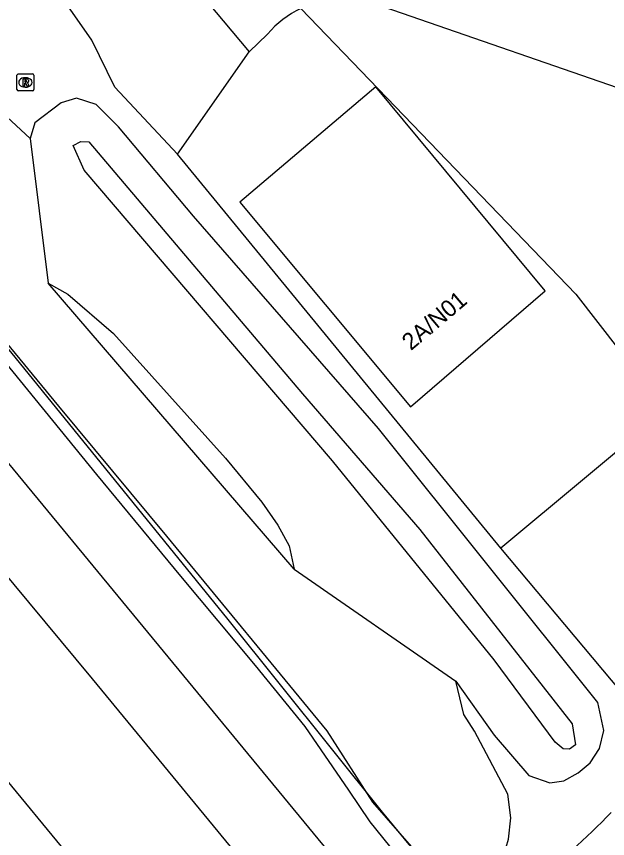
# Model space of a CAD drawing. Extents: x 158132 to 159658, y 385257 to 387209.
# Drawn here: x 159265.1 to 159300.11, y 385281.7 to 385330.4 of the extents above; entities that cross this region are included whole.
import ezdxf

# ---------------------------------------------------------------- set-up
doc = ezdxf.new("R2010")
doc.units = 0
for name, color, linetype in [('IMGEO_Geluidsscherm', 7, 'Continuous'), ('IMGEO_Grasland_overig', 7, 'Continuous'), ('IMGEO_Groenvoorziening', 7, 'Continuous'), ('IMGEO_Pand', 7, 'Continuous'), ('IMGEO_Pand_nummerreeks', 7, 'Continuous'), ('IMGEO_Rijbaan_lokaal_gesloten', 7, 'Continuous'), ('IMGEO_Rijbaan_lokaal_open', 7, 'Continuous'), ('IMGEO_Rioolput', 7, 'Continuous'), ('IMGEO_Spoor', 7, 'Continuous'), ('IMGEO_Spoorbaan_halfverhard', 7, 'Continuous'), ('IMGEO_Struiken', 7, 'Continuous'), ('IMGEO_Voetpad_open', 7, 'Continuous'), ('IMGEO_Waterloop', 7, 'Continuous')]:
    doc.layers.add(name, color=color, linetype=linetype)

msp = doc.modelspace()

# ---------------------------------------------------------------- linework, layer by layer
at = {"layer": 'IMGEO_Geluidsscherm'}
for points in [[(159286.211, 385283.865), (159283.499, 385288.078), (159274.005, 385299.62), (159267.615, 385307.323), (159258.062, 385318.911), (159242.144, 385338.211), (159232.644, 385349.825), (159223.238, 385361.455), (159210.649, 385376.979), (159201.186, 385388.692), (159191.801, 385400.335), (159182.407, 385412.048), (159166.93, 385431.293), (159161.29, 385438.364)], [(159296.997, 385270.945), (159292.991, 385275.788), (159288.498, 385281.229), (159286.211, 385283.865)]]:
    msp.add_lwpolyline(points, dxfattribs=at)
at = {"layer": 'IMGEO_Grasland_overig'}
for points in [[(159291.119, 385291.018), (159293.396, 385287.829), (159295.457, 385285.447), (159296.697, 385285.002), (159297.523, 385285.119), (159298.364, 385285.595), (159299.082, 385286.185), (159299.634, 385287.039), (159299.891, 385288.107), (159299.54, 385289.761), (159286.549, 385305.997), (159275.58, 385318.577), (159271.141, 385323.855), (159269.821, 385325.184), (159268.653, 385325.56), (159267.742, 385325.27), (159266.182, 385324.102), (159265.905, 385323.162)], [(159293.797, 385298.904), (159274.632, 385322.244)], [(159266.982, 385314.602), (159268.141, 385313.945), (159270.859, 385311.624), (159277.476, 385304.236), (159279.635, 385301.634), (159280.576, 385300.258), (159281.255, 385299.039), (159281.559, 385297.663)], [(159303.628, 385287.17), (159293.797, 385298.904)]]:
    msp.add_lwpolyline(points, dxfattribs=at)
at = {"layer": 'IMGEO_Groenvoorziening'}
msp.add_lwpolyline([(159281.95, 385330.865), (159298.235, 385313.951), (159303.578, 385307.059), (159293.797, 385298.904)], dxfattribs=at)
at = {"layer": 'IMGEO_Pand'}
msp.add_lwpolyline([(159286.379, 385326.224), (159278.322, 385319.396), (159288.437, 385307.269), (159296.42, 385314.151), (159286.379, 385326.224)], dxfattribs=at)
at = {"layer": 'IMGEO_Rijbaan_lokaal_gesloten'}
for points in [[(159271.887, 385336.661), (159278.893, 385328.292)], [(159274.632, 385322.244), (159270.926, 385326.201), (159269.57, 385328.991), (159267.594, 385331.826), (159265.132, 385334.674)], [(159274.632, 385322.244), (159278.893, 385328.292)]]:
    msp.add_lwpolyline(points, dxfattribs=at)
at = {"layer": 'IMGEO_Rijbaan_lokaal_open'}
for points in [[(159312.983, 385321.919), (159302.29, 385325.612), (159286.875, 385330.944), (159286.667, 385331.008)], [(159278.893, 385328.292), (159279.968, 385329.356)]]:
    msp.add_lwpolyline(points, dxfattribs=at)
msp.add_arc((159284.468, 385325.502), 5.925, 115.1483, 139.4196, dxfattribs=at)
at = {"layer": 'IMGEO_Rioolput'}
for p, q in [((159265.133, 385326.062), (159265.133, 385326.914)), ((159265.208, 385326.988), (159266.06, 385326.988)), ((159265.621, 385326.768), (159265.646, 385326.768)), ((159266.134, 385326.914), (159266.134, 385326.062)), ((159265.644, 385326.208), (159265.619, 385326.208)), ((159266.06, 385325.988), (159265.208, 385325.988))]:
    msp.add_line(p, q, dxfattribs=at)
for points in [[(159265.133, 385326.062), (159265.133, 385326.914)], [(159265.208, 385326.988), (159266.06, 385326.988)], [(159265.722, 385326.686), (159265.47, 385326.688), (159265.47, 385326.288)], [(159266.134, 385326.914), (159266.134, 385326.062)], [(159265.47, 385326.288), (159265.594, 385326.288), (159265.594, 385326.45), (159265.605, 385326.45)], [(159265.648, 385326.607), (159265.594, 385326.607), (159265.594, 385326.526)], [(159265.594, 385326.526), (159265.646, 385326.526)], [(159265.652, 385326.421), (159265.723, 385326.288), (159265.863, 385326.288), (159265.798, 385326.414)], [(159266.06, 385325.988), (159265.208, 385325.988)]]:
    msp.add_lwpolyline(points, dxfattribs=at)
for centre, radius, start, end in [((159265.21, 385326.912), 0.0765, 91.552, 178.448), ((159265.21, 385326.912), 0.0765, 91.552, 178.448), ((159265.721, 385326.576), 0.109, 350.3612, 89.416), ((159266.058, 385326.912), 0.0765, 1.552, 88.448), ((159266.058, 385326.912), 0.0765, 1.552, 88.448), ((159265.604, 385326.397), 0.0533, 26.0293, 88.6989), ((159265.63, 385326.715), 0.19, 274.7715, 282.9687), ((159265.654, 385326.511), 0.0964, 77.0061, 93.1865), ((159265.668, 385326.568), 0.0378, 276.6634, 79.6772), ((159265.719, 385326.576), 0.112, 277.5842, 350.9817), ((159265.703, 385326.361), 0.108, 29.5134, 73.7905), ((159265.21, 385326.064), 0.0765, 181.552, 268.448), ((159265.21, 385326.064), 0.0765, 181.552, 268.448), ((159266.058, 385326.064), 0.0765, 271.552, 358.448), ((159266.058, 385326.064), 0.0765, 271.552, 358.448)]:
    msp.add_arc(centre, radius, start, end, dxfattribs=at)
for centre, major_axis, ratio, start_param, end_param in [((159265.62, 385326.488), (-0.387, 0.002), 0.722429, 4.712389, 7.853982), ((159265.645, 385326.488), (-0.39, 0.002), 0.717154, 1.570796, 4.712389)]:
    msp.add_ellipse(centre, major_axis=major_axis, ratio=ratio, start_param=start_param, end_param=end_param, dxfattribs=at)
at = {"layer": 'IMGEO_Spoor'}
for points in [[(158305.016, 386458.213), (158323.798, 386435.605), (158392.217, 386352.854), (158899.464, 385738.82), (158924.542, 385708.133), (158959.679, 385664.771), (158977.24, 385642.932), (159021.108, 385587.171), (159057.713, 385540.324), (159087.551, 385502.294), (159118.562, 385463.178), (159158.867, 385413.287), (159192.222, 385372.584), (159280.072, 385266.342)], [(158391.093, 386360.722), (158491.126, 386239.561), (158538.065, 386183.03), (158587.156, 386123.489), (158724.168, 385957.812), (158781.971, 385887.68), (158833.112, 385825.865), (158873.914, 385776.355), (158947.251, 385687.779), (158974.976, 385654.087), (158999.799, 385623.885), (159031.623, 385584.845), (159070.241, 385536.675), (159150.393, 385436.396), (159181.354, 385398.007), (159212.164, 385360.435), (159269.577, 385291.155), (159286.01, 385271.253)], [(158467.756, 386280.045), (158481.705, 386263.375), (158516.185, 386221.439), (158744.019, 385945.816), (158789.16, 385891.013), (158837.921, 385832.197), (158939.856, 385708.893), (158979.907, 385660.121), (159034.297, 385592.754), (159082.736, 385531.413), (159124.365, 385478.038), (159172.246, 385417.353), (159208.964, 385371.653), (159261.543, 385307.652), (159289.313, 385273.985)]]:
    msp.add_lwpolyline(points, dxfattribs=at)
at = {"layer": 'IMGEO_Spoorbaan_halfverhard'}
msp.add_lwpolyline([(159291.594, 385275.872), (159288.8, 385279.308), (159286.058, 385282.697), (159284.78, 385284.564), (159282.209, 385288.341), (159279.251, 385291.96), (159274.842, 385297.238), (159269.866, 385303.262), (159263.59, 385310.945), (159244.196, 385334.345), (159232.507, 385348.591), (159206.55, 385380.572), (159185.763, 385406.507), (159148.727, 385453.136), (159124.975, 385483.164)], dxfattribs=at)
at = {"layer": 'IMGEO_Struiken'}
for points in [[(159265.905, 385323.162), (159263.712, 385325.202), (159263.107, 385326.007), (159262.224, 385327.59)], [(159265.905, 385323.162), (159266.982, 385314.602)], [(159281.559, 385297.663), (159266.982, 385314.602)], [(159261.75, 385314.034), (159264.742, 385310.529), (159277.618, 385294.686), (159286.766, 385283.276), (159291.797, 385277.162)], [(159281.559, 385297.663), (159291.119, 385291.018)], [(159291.797, 385277.162), (159293.003, 385278.596), (159293.828, 385280.242), (159294.249, 385281.665), (159294.389, 385282.923), (159294.206, 385284.343), (159292.221, 385288.06), (159291.601, 385289.055), (159291.119, 385291.018)]]:
    msp.add_lwpolyline(points, dxfattribs=at)
at = {"layer": 'IMGEO_Voetpad_open'}
msp.add_arc((159271.74, 385310.718), 39.642, 306.8565, 316.1514, dxfattribs=at)
at = {"layer": 'IMGEO_Waterloop'}
msp.add_lwpolyline([(159293.402, 385292.287), (159283.816, 385304.081), (159269.104, 385321.282), (159268.455, 385322.757), (159268.914, 385322.984), (159269.383, 385322.96), (159282.047, 385308.038), (159288.986, 385300.01), (159298.023, 385288.492), (159298.214, 385287.252), (159297.854, 385286.993), (159297.481, 385287.025), (159297.005, 385287.419), (159293.402, 385292.287)], dxfattribs=at)

# ---------------------------------------------------------------- texts
at = {"layer": 'IMGEO_Pand_nummerreeks'}
msp.add_text('2A/N01', height=1, rotation=40.1701, dxfattribs=at).set_placement((159288.463, 385310.57))

doc.saveas('drawing.dxf')
